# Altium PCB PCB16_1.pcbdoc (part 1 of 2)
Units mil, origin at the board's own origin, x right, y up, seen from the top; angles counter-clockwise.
Board outline 5590 x 7095 mil, 2 copper layers (Top Layer, Bottom Layer); 147 components, 87 nets, 409 pads, 337 vias.
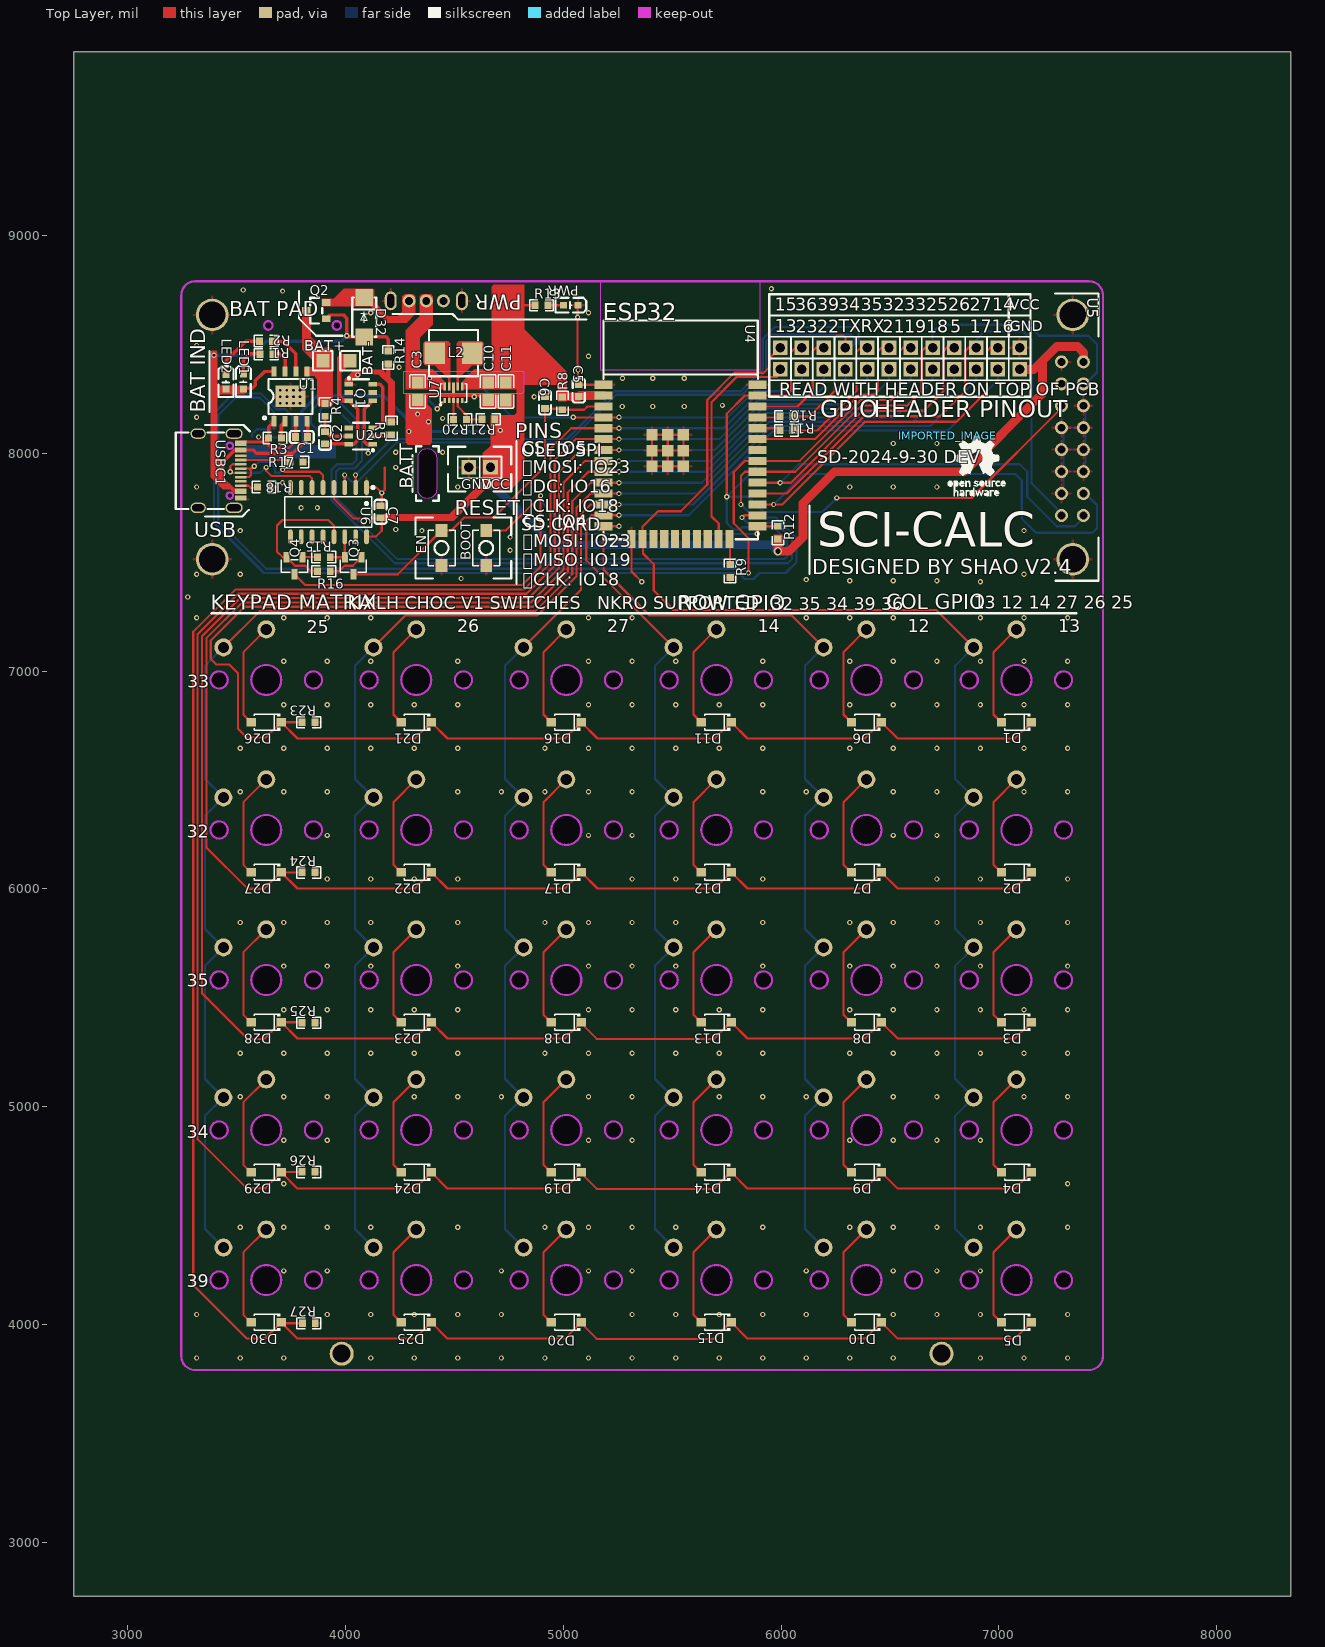
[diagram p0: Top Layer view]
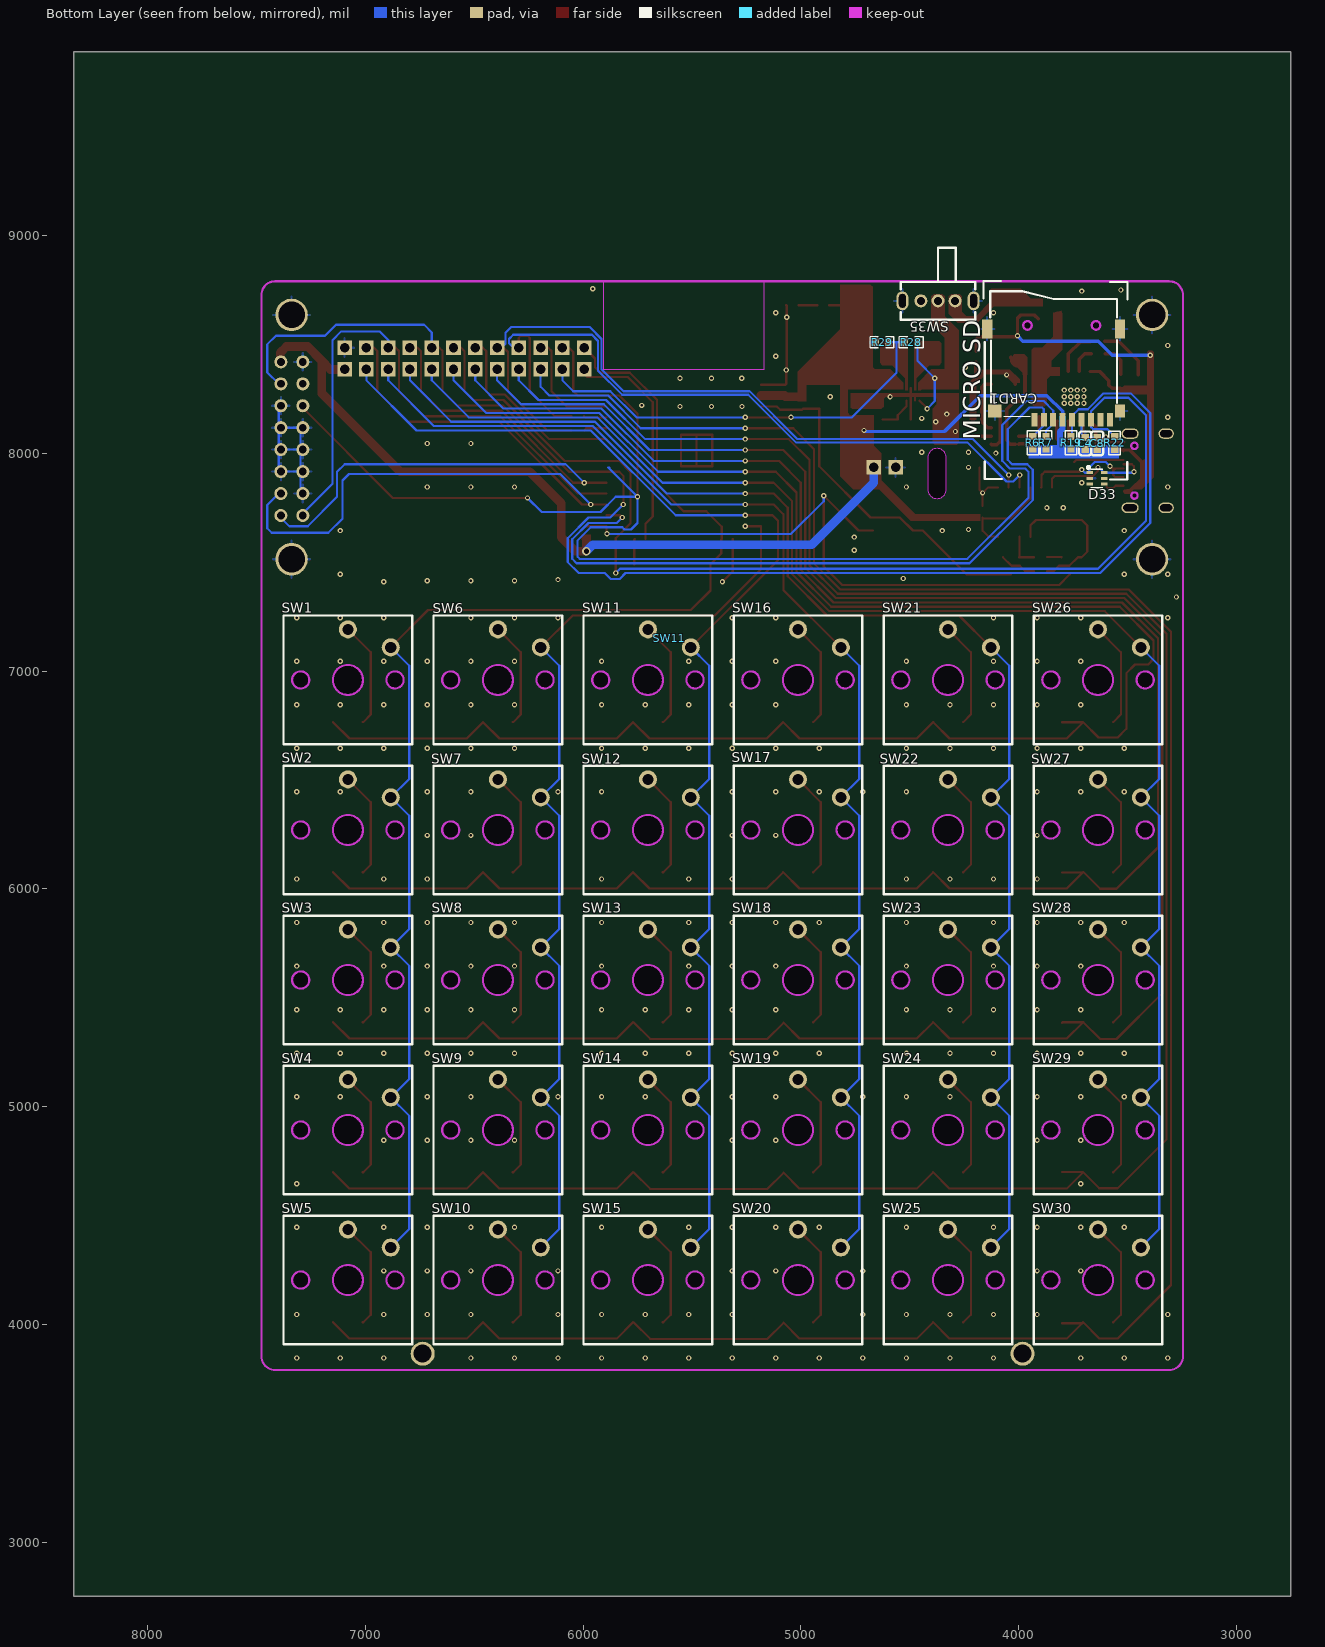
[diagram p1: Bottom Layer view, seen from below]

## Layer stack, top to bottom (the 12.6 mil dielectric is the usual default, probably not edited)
Top Layer: signal copper (thickness not stored)
Dielectric: dielectric 12.6, FR-4, Dk 4.8
Bottom Layer: signal copper (thickness not stored)

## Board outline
8340,2750 2750,2750 2750,9845 8340,9845
cut-out: 4332.03,7834.53 4332.03,7979.53 cw(c4374.53,7979.53) 4374.53,8022.03 cw(c4374.53,7979.53) 4417.03,7979.53 4417.03,7834.53 cw(c4374.53,7834.53) 4374.53,7792.03 cw(c4374.53,7834.53)

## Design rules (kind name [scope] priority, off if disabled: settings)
Clearance safeClearance [All] p1: gap=7 ignorepadtopadclearanceinfootprint=FALSE except(6: Track-Track Track-SMDPad SMDPad-SMDPad Track-THPad SMDPad-THPad THPad-THPad Track-Via SMDPad-Via THPad-Via Via-Via Track-Fill SMDPad-Fill THPad-Fill Via-Fill Fill-Fill Track-Region SMDPad-Region THPad-Region Via-Region Fill-Region Region-Region Track-Poly SMDPad-Poly THPad-Poly Via-Poly Fill-Poly Region-Poly Poly-Poly Track-Text SMDPad-Text THPad-Text Via-Text Fill-Text Region-Text Poly-Text Text-Text Track-Hole SMDPad-Hole THPad-Hole Via-Hole Fill-Hole Region-Hole Poly-Hole Text-Hole; 11.8: Track-Sheet SMDPad-Sheet THPad-Sheet Via-Sheet Fill-Sheet Region-Sheet Poly-Sheet Text-Sheet Sheet-Hole)
DiffPairsRouting differentialPair [All] p1: maxuncoupledlength=10 minlimit=6 maxlimit=50 mostfreqgap=6 toplayer_minwidth=5 toplayer_prefwidth=10 toplayer_maxwidth=100 bottomlayer_minwidth=5 bottomlayer_prefwidth=10 bottomlayer_maxwidth=100
PasteMaskExpansion pasteMaskExpansion [All] p1:
PlaneConnect innerPlane [All] p1: planeconnectstyle=Relief reliefexpansion=20 reliefentries=4 reliefconductorwidth=10 reliefairgap=10
PolygonConnect copperRegion [All] p1: connectstyle=Relief reliefentries=4 reliefconductorwidth=10 polygonreliefangle="90 Angle" airgapwidth=10
RoutingVias viaSize [All] p1: viastyle="Through Hole" holewidth=12.0078 minholewidth=11.811 maxholewidth=236.2204 width=24.0158 minwidth=19.685 maxwidth=393.7008
SolderMaskExpansion solderMaskExpansion [All] p1: useseparateexpansions=TRUE expansion=4 expansionbottom=4
Width trackWidth [All] p1: maxlimit=100 minlimit=5 preferedwidth=10

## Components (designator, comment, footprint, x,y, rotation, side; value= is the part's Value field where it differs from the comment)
5 "2.54-1*1P针" HDR-TH_1P-P2.54-V-M 6795,8485 r0 top
13 "2.54-1*1P针" HDR-TH_1P-P2.54-V-M 5995,8485 r0 top
14 "2.54-1*1P针" HDR-TH_1P-P2.54-V-M 6995,8385 r180 top
15 "2.54-1*1P针" HDR-TH_1P-P2.54-V-M 5995,8385 r0 top
16 "2.54-1*1P针" HDR-TH_1P-P2.54-V-M 6995,8485 r0 top
17 "2.54-1*1P针" HDR-TH_1P-P2.54-V-M 6895,8485 r0 top
18 "2.54-1*1P针" HDR-TH_1P-P2.54-V-M 6695,8485 r0 top
19 "2.54-1*1P针" HDR-TH_1P-P2.54-V-M 6595,8485 r0 top
21 "2.54-1*1P针" HDR-TH_1P-P2.54-V-M 6495,8485 r0 top
22 "2.54-1*1P针" HDR-TH_1P-P2.54-V-M 6195,8485 r0 top
23 "2.54-1*1P针" HDR-TH_1P-P2.54-V-M 6095,8485 r0 top
25 "2.54-1*1P针" HDR-TH_1P-P2.54-V-M 6695,8385 r0 top
26 "2.54-1*1P针" HDR-TH_1P-P2.54-V-M 6795,8385 r0 top
27 "2.54-1*1P针" HDR-TH_1P-P2.54-V-M 6895,8385 r0 top
32 "2.54-1*1P针" HDR-TH_1P-P2.54-V-M 6495,8385 r0 top
33 "2.54-1*1P针" HDR-TH_1P-P2.54-V-M 6595,8385 r0 top
34 "2.54-1*1P针" HDR-TH_1P-P2.54-V-M 6295,8385 r0 top
35 "2.54-1*1P针" HDR-TH_1P-P2.54-V-M 6395,8385 r0 top
36 "2.54-1*1P针" HDR-TH_1P-P2.54-V-M 6095,8385 r180 top
39 "2.54-1*1P针" HDR-TH_1P-P2.54-V-M 6195,8385 r0 top
BOOT "TS-1088-AR02016" SW-SMD_L4.0-W2.9-LS5.0 4645,7565 r90 top
C1 "CL10A106KP8NNNC" C0603 3797.56,8075 r180 top
C2 "CC0603KRX7R9BB104" C0603 3904.99,8071.44 r90 top
C3 "CL21A106KAYNNNE_C15850" C0805 4330,8284.45 r90 top
C4 "CC0603KRX7R9BB104" C0603 3694.07,8045.21 r270 bottom
C5 "CC0603KRX7R9BB104" C0603 5070,8287.56 r270 top
C6 "CL10A106KP8NNNC" C0603 4915,8232.44 r270 top
C7 "CC0603KRX7R9BB104" C0603 4160.16,7731.31 r270 top
C8 "CC0603KRX7R9BB104" C0603 3639.07,8045.33 r270 bottom
C10 "CL21A226MAQNNNE_C45783" C0805 4653.82,8284.45 r90 top
C11 "CL21A226MAQNNNE_C45783" C0805 4735.57,8284.2 r90 top
CARD1 "TF-01A_C2889258" TF-SMD_TF-02 3839.07,8362.77 r0 bottom
D1 "1N4148W_C81598" SOD-123F_L2.7-W1.6-LS3.8-RD 7079.97,6765.24 r180 top
D2 "1N4148W_C81598" SOD-123F_L2.7-W1.6-LS3.8-RD 7079.97,6076.26 r180 top
D3 "1N4148W_C81598" SOD-123F_L2.7-W1.6-LS3.8-RD 7079.97,5387.28 r180 top
D4 "1N4148W_C81598" SOD-123F_L2.7-W1.6-LS3.8-RD 7079.97,4698.31 r180 top
D5 "1N4148W_C81598" SOD-123F_L2.7-W1.6-LS3.8-RD 7079.97,4009.33 r180 top
D6 "1N4148W_C81598" SOD-123F_L2.7-W1.6-LS3.8-RD 6390.99,6765.24 r180 top
D7 "1N4148W_C81598" SOD-123F_L2.7-W1.6-LS3.8-RD 6390.99,6076.26 r180 top
D8 "1N4148W_C81598" SOD-123F_L2.7-W1.6-LS3.8-RD 6390.99,5387.28 r180 top
D9 "1N4148W_C81598" SOD-123F_L2.7-W1.6-LS3.8-RD 6390.99,4698.31 r180 top
D10 "1N4148W_C81598" SOD-123F_L2.7-W1.6-LS3.8-RD 6390.99,4009.33 r180 top
D11 "1N4148W_C81598" SOD-123F_L2.7-W1.6-LS3.8-RD 5702.02,6765.24 r180 top
D12 "1N4148W_C81598" SOD-123F_L2.7-W1.6-LS3.8-RD 5702.02,6076.26 r180 top
D13 "1N4148W_C81598" SOD-123F_L2.7-W1.6-LS3.8-RD 5702.02,5387.28 r180 top
D14 "1N4148W_C81598" SOD-123F_L2.7-W1.6-LS3.8-RD 5702.02,4698.31 r180 top
D15 "1N4148W_C81598" SOD-123F_L2.7-W1.6-LS3.8-RD 5702.02,4009.33 r180 top
D16 "1N4148W_C81598" SOD-123F_L2.7-W1.6-LS3.8-RD 5013.04,6765.24 r180 top
D17 "1N4148W_C81598" SOD-123F_L2.7-W1.6-LS3.8-RD 5013.04,6076.26 r180 top
D18 "1N4148W_C81598" SOD-123F_L2.7-W1.6-LS3.8-RD 5013.04,5387.28 r180 top
D19 "1N4148W_C81598" SOD-123F_L2.7-W1.6-LS3.8-RD 5013.04,4698.31 r180 top
D20 "1N4148W_C81598" SOD-123F_L2.7-W1.6-LS3.8-RD 5013.04,4009.33 r180 top
D21 "1N4148W_C81598" SOD-123F_L2.7-W1.6-LS3.8-RD 4324.06,6765.24 r180 top
D22 "1N4148W_C81598" SOD-123F_L2.7-W1.6-LS3.8-RD 4324.06,6076.26 r180 top
D23 "1N4148W_C81598" SOD-123F_L2.7-W1.6-LS3.8-RD 4324.06,5387.28 r180 top
D24 "1N4148W_C81598" SOD-123F_L2.7-W1.6-LS3.8-RD 4324.06,4698.31 r180 top
D25 "1N4148W_C81598" SOD-123F_L2.7-W1.6-LS3.8-RD 4324.06,4009.33 r180 top
D26 "1N4148W_C81598" SOD-123F_L2.7-W1.6-LS3.8-RD 3635.09,6765.24 r180 top
D27 "1N4148W_C81598" SOD-123F_L2.7-W1.6-LS3.8-RD 3635.09,6076.26 r180 top
D28 "1N4148W_C81598" SOD-123F_L2.7-W1.6-LS3.8-RD 3635.09,5387.28 r180 top
D29 "1N4148W_C81598" SOD-123F_L2.7-W1.6-LS3.8-RD 3635.09,4698.31 r180 top
D30 "1N4148W_C81598" SOD-123F_L2.7-W1.6-LS3.8-RD 3635.09,4009.33 r180 top
D32 "SS34_C8678" DO-214AC_L4.3-W2.7-LS5.3-RD 4085,8625 r270 top
D33 "TPD4E1U06DCKR" SC-70-6_L2.2-W1.3-P0.65-LS2.1-BL 3640,7885 r270 bottom
EN "TS-1088-AR02016" SW-SMD_L4.0-W2.9-LS5.0 4440,7565 r90 top
GND "2.54-1*1P针" HDR-TH_1P-P2.54-V-M 4565,7935 r90 top
GND "2.54-1*1P针" HDR-TH_1P-P2.54-V-M 7095,8485 r0 top
IMPORTED_IMAGE "IMPORTED_IMAGE" IMPORTED_IMAGE 6765,8080 r0 top
L2 "MHCI05030-R47M-R8" IND-SMD_L5.7-W5.4 4495,8460 r0 top
LED1 "19-217/R6C-AL1M2VY/3T" LED0603-R-RD 3530.12,8329.39 r270 top
LED2 "19-217/GHC-YR1S2/3T" LED0603-R-RD 3450.12,8327.89 r270 top
PWR "19-217/R6C-AL1M2VY/3T" LED0603-R-RD 5033.5,8680 r180 top
Q1 "FS8205" SOT-23-6_L2.9-W1.6-P0.95-LS2.8-BR 4069.99,8279 r180 top
Q2 "AO3401A_C15127" SOT-23_L2.9-W1.3-P1.90-LS2.4-BR 3865,8655 r0 top
Q3 "S8050" SOT-23-3_L2.9-W1.3-P1.90-LS2.4-BR 4034.74,7483.33 r90 top
Q4 "S8050" SOT-23-3_L2.9-W1.3-P1.90-LS2.4-BR 3764.74,7483.33 r90 top
R1 "RC0603FR-071KL" R0603 3635.34,8455 r180 top
R2 "RC0603FR-071KL" R0603 3634.66,8515 r0 top
R3 "AR03BTCX5001" R0603 3675,8070 r0 top
R4 "RC0603FR-07100RL" R0603 3905,8199.66 r90 top
R5 "RC0603FR-072KL" R0603 4210,8114.66 r270 top
R6 "RC0603FR-0710KL" R0603 3934.07,8048.11 r270 bottom
R7 "RC0603FR-0710KL" R0603 3874.07,8048.11 r270 bottom
R8 "RC0603FR-0710KL" R0603 4995,8229.66 r90 top
R9 "RC0603FR-0710KL" R0603 5765,7459.66 r90 top
R10 "RC0603FR-07100RL" R0603 6024.66,8170 r180 top
R11 "RC0603FR-07100RL" R0603 6024.66,8105 r180 top
R12 "TR0603B10K0P0525Z" R0603 5985,7635.34 r90 top
R13 "RC0603FR-071KL" R0603 4899.66,8680 r0 top
R14 "RC0603FR-0710KL" R0603 4195,8439.66 r90 top
R15 "TR0603B10K0P0525Z" R0603 3899.4,7458.33 r180 top
R16 "TR0603B10K0P0525Z" R0603 3899.4,7523.33 r0 top
R17 "0603WAF5101T5E" R0603 3774.66,7960 r0 top
R18 "0603WAF5101T5E" R0603 3625,7845 r180 top
R19 "RC0603FR-0710KL" R0603 3759.07,8048.11 r270 bottom
R20 "0603WAF9102T5E" R0603 4524.66,8155 r180 top
R21 "0603WAF5113T5E" R0603 4654.66,8156 r0 top
R22 "RC0603FR-0710KL" R0603 3559.07,8047.43 r270 bottom
R23 "TR0603B10K0P0525Z" R0603 3829.66,6765 r180 top
R24 "TR0603B10K0P0525Z" R0603 3829.66,6075 r180 top
R25 "TR0603B10K0P0525Z" R0603 3829.66,5385 r180 top
R26 "TR0603B10K0P0525Z" R0603 3829.66,4700 r180 top
R27 "TR0603B10K0P0525Z" R0603 3830.34,4005 r180 top
R28 "100k" R0603 4493.24,8509.76 r180 bottom
R29 "100k" R0603 4626.91,8509.76 r180 bottom
RX "2.54-1*1P针" HDR-TH_1P-P2.54-V-M 6395,8485 r180 top
SW1 "CPG135001D01" KEY-TH_CPG135001D0X 6981.58,7150 r180 bottom
SW2 "CPG135001D01" KEY-TH_CPG135001D0X 6981.58,6461.02 r180 bottom
SW3 "CPG135001D01" KEY-TH_CPG135001D0X 6981.58,5772.05 r180 bottom
SW4 "CPG135001D01" KEY-TH_CPG135001D0X 6981.58,5083.07 r180 bottom
SW5 "CPG135001D01" KEY-TH_CPG135001D0X 6981.58,4394.09 r180 bottom
SW6 "CPG135001D01" KEY-TH_CPG135001D0X 6292.61,7150 r180 bottom
SW7 "CPG135001D01" KEY-TH_CPG135001D0X 6292.61,6461.02 r180 bottom
SW8 "CPG135001D01" KEY-TH_CPG135001D0X 6292.61,5772.05 r180 bottom
SW9 "CPG135001D01" KEY-TH_CPG135001D0X 6292.61,5083.07 r180 bottom
SW10 "CPG135001D01" KEY-TH_CPG135001D0X 6292.61,4394.09 r180 bottom
SW11 "CPG135001D01" KEY-TH_CPG135001D0X 5603.63,7150 r180 bottom
SW12 "CPG135001D01" KEY-TH_CPG135001D0X 5603.63,6461.02 r180 bottom
SW13 "CPG135001D01" KEY-TH_CPG135001D0X 5603.63,5772.05 r180 bottom
SW14 "CPG135001D01" KEY-TH_CPG135001D0X 5603.63,5083.07 r180 bottom
SW15 "CPG135001D01" KEY-TH_CPG135001D0X 5603.63,4394.09 r180 bottom
SW16 "CPG135001D01" KEY-TH_CPG135001D0X 4914.65,7150 r180 bottom
SW17 "CPG135001D01" KEY-TH_CPG135001D0X 4914.65,6461.02 r180 bottom
SW18 "CPG135001D01" KEY-TH_CPG135001D0X 4914.65,5772.05 r180 bottom
SW19 "CPG135001D01" KEY-TH_CPG135001D0X 4914.65,5083.07 r180 bottom
SW20 "CPG135001D01" KEY-TH_CPG135001D0X 4914.65,4394.09 r180 bottom
SW21 "CPG135001D01" KEY-TH_CPG135001D0X 4225.68,7150 r180 bottom
SW22 "CPG135001D01" KEY-TH_CPG135001D0X 4225.68,6461.02 r180 bottom
SW23 "CPG135001D01" KEY-TH_CPG135001D0X 4225.68,5772.05 r180 bottom
SW24 "CPG135001D01" KEY-TH_CPG135001D0X 4225.68,5083.07 r180 bottom
SW25 "CPG135001D01" KEY-TH_CPG135001D0X 4225.68,4394.09 r180 bottom
SW26 "CPG135001D01" KEY-TH_CPG135001D0X 3536.7,7150 r180 bottom
SW27 "CPG135001D01" KEY-TH_CPG135001D0X 3536.7,6461.02 r180 bottom
SW28 "CPG135001D01" KEY-TH_CPG135001D0X 3536.7,5772.05 r180 bottom
SW29 "CPG135001D01" KEY-TH_CPG135001D0X 3536.7,5083.07 r180 bottom
SW30 "CPG135001D01" KEY-TH_CPG135001D0X 3536.7,4394.09 r180 bottom
SW35 "SK12D07VG4" SW-TH_SK12D07VG4 4370,8700 r0 bottom
TX "2.54-1*1P针" HDR-TH_1P-P2.54-V-M 6295,8485 r180 top
U1 "4056" ESOP-8_L4.9-W3.9-P1.27-LS6.0-BL-EP 3746.43,8261.1 r0 top
U2 "DW01" SOT-23-6_L2.9-W1.6-P0.95-LS2.8-BR 4069.99,8079 r0 top
U4 "ESP32-WROOM-32E-H4" WIFI-SMD_ESP32-WROOM-32E 5537.78,7960.59 r270 top
U5 "oled" oled3.1 3500,7415 r0 top
U6 "CH340C" SOP-16_L10.0-W3.9-P1.27-LS6.0-BL 3920.76,7729.66 r180 top
U7 "TPS63802DLAR_C2845237" VSON-10_L3.0-W2.0-P0.50-TL 4495,8274.61 r90 top
USBC1 "TYPE-C-31-M-12" USB-C_SMD-TYPE-C-31-M-12 3420,7920 r270 top
VCC "2.54-1*1P针" HDR-TH_1P-P2.54-V-M 4665,7935 r0 top
VCC "2.54-1*1P针" HDR-TH_1P-P2.54-V-M 7095,8385 r0 top

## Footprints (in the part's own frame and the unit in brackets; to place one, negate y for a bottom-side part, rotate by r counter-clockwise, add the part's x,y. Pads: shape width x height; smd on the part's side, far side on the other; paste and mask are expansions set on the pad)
C0603 [mm]
  rect 0.8x0.9 smd: 1(-0.7,0) 2(0.7,0)
  silkscreen extent -1.41,-0.71 1.39,0.72
C0805 [mm]
  rect 1.41x1.35 smd: 1(-1.03,0) 2(1.03,0)
  silkscreen extent -1.96,-0.9 1.96,0.9
DO-214AC_L4.3-W2.7-LS5.3-RD [mil]
  rect 78.7x78.7 smd: 1(-90.5,0) 2(90.6,0)
  silkscreen extent -91,-55 91,55
ESOP-8_L4.9-W3.9-P1.27-LS6.0-BL-EP [mm]
  rect 0.6x1.2 smd: 1(-1.905,-2.908) 2(-0.635,-2.908) 3(0.635,-2.908) 4(1.905,-2.908) 5(1.905,2.908) 6(0.635,2.908) 7(-0.635,2.908) 8(-1.905,2.908)
  rect 3.5x2.5 smd: 9(0,0)
  silkscreen extent -3.2,-2.67 2.55,2.05
HDR-TH_1P-P2.54-V-M [mm]
  rect 1.7x1.7 hole 1.1: 1(0,0)
  silkscreen extent -1.27,-1.27 1.27,1.27
IMPORTED_IMAGE [mil]
  silkscreen extent 0,-277 265,0
IND-SMD_L5.7-W5.4 [mil]
  rect 94.5x98.4 smd: 1(-86.6,0) 2(86.6,0)
  silkscreen extent -112,-106 112,106
KEY-TH_CPG135001D0X [mil]
  round 82.7 hole 51.2: 1(-98.4,41.3) 2(98.4,-41.3)
  Multi-Layer board cut-out: -167.3,-190.9 -160.48,-161.01 -141.36,-137.03 -113.73,-123.73 -83.07,-123.73 -55.44,-137.03 -36.32,-161.01 -29.5,-190.9 -29.5,-190.9 -36.32,-220.79 -55.44,-244.77 -83.07,-258.07 -113.73,-258.07 -141.36,-244.77 -160.48,-220.79 -167.3,-190.9
  Multi-Layer board cut-out: -354.4,-190.9 -350.5,-173.8 -339.57,-160.1 -323.77,-152.49 -306.23,-152.49 -290.43,-160.1 -279.5,-173.8 -275.6,-190.9 -275.6,-190.9 -279.5,-208 -290.43,-221.7 -306.23,-229.31 -323.77,-229.31 -339.57,-221.7 -350.5,-208 -354.4,-190.9
  Multi-Layer board cut-out: 78.7,-190.9 82.6,-173.8 93.53,-160.1 109.33,-152.49 126.87,-152.49 142.67,-160.1 153.6,-173.8 157.5,-190.9 157.5,-190.9 153.6,-208 142.67,-221.7 126.87,-229.31 109.33,-229.31 93.53,-221.7 82.6,-208 78.7,-190.9
  Multi-Layer keep-out circle w10: c-98.4,-190.9 r68.9
  Multi-Layer keep-out circle w10: c-315,-190.9 r39.4
  Multi-Layer keep-out circle w10: c118.1,-190.9 r39.4
  silkscreen extent -394,-486 197,104
LED0603-R-RD [mm]
  rect 0.8x0.8 smd: 1(0.851,0) 2(-0.851,0)
  silkscreen extent -1.82,-0.86 1.77,0.86
oled3.1 [mil]
  round 60 hole 35.98: 1(3787.01,1004.8) 2(3887.8,1004.8) 3(3787.01,904.02) 4(3887.8,904.02) 5(3787.01,803.23) 6(3887.8,803.23) 7(3787.01,702.44) 8(3887.8,702.44) 9(3787.01,601.65) 10(3887.8,601.65) 11(3787.01,500.87) 12(3887.8,500.87) 13(3787.01,400.08) 14(3887.8,400.08) 15(3787.01,299.29) 16(3887.8,299.29)
  silkscreen extent 3758,0 3957,1319
R0603 [mil]
  rect 31.75x34.02 smd: 1(-29.66,0) 2(29.66,0)
  silkscreen extent -55,-26 55,26
SC-70-6_L2.2-W1.3-P0.65-LS2.1-BL [mm]
  rect 0.35x0.78 smd: 1(-0.65,-0.84) 2(0,-0.84) 3(0.65,-0.84) 4(0.65,0.84) 5(0,0.84) 6(-0.65,0.84)
  silkscreen extent -1.43,-1.14 1.08,0.7
SOD-123F_L2.7-W1.6-LS3.8-RD [mm]
  rect 1.1x1 smd: 1(-1.735,0) 2(1.735,0)
  silkscreen extent -1.6,-1 1.38,1
SOP-16_L10.0-W3.9-P1.27-LS6.0-BL [mm]
  oval 0.56x1.745 smd: 1(-4.445,-2.872) 2(-3.175,-2.872) 3(-1.905,-2.872) 4(-0.635,-2.872) 5(0.635,-2.872) 6(1.905,-2.872) 7(3.175,-2.872) 8(4.445,-2.872) 9(4.445,2.872) 10(3.175,2.872) 11(1.905,2.872) 12(0.635,2.872) 13(-0.635,2.872) 14(-1.905,2.872) 15(-3.175,2.872) 16(-4.445,2.872)
  silkscreen extent -5.33,-3.02 5.08,1.77
SOT-23-3_L2.9-W1.3-P1.90-LS2.4-BR [mm]
  rect 1.25x0.7 smd: 1(1,-0.95) 2(1,0.95) 3(-1,0)
  silkscreen extent -0.73,-1.53 0.73,1.53
SOT-23-6_L2.9-W1.6-P0.95-LS2.8-BR [mm]
  rect 1x0.55 smd: 1(1.4,-0.95) 2(1.4,0) 3(1.4,0.95) 4(-1.4,0.95) 5(-1.4,0) 6(-1.4,-0.95)
  silkscreen extent -0.9,-1.78 1.52,1.55
SOT-23_L2.9-W1.3-P1.90-LS2.4-BR [mm]
  rect 1x0.8 smd: 1(1.15,-0.95) 2(1.15,0.95) 3(-1.15,0)
  silkscreen extent -0.7,-1.5 0.7,1.5
SW-SMD_L4.0-W2.9-LS5.0 [mm]
  rect 1.53x1.36 smd: 1(-2.035,0) 2(2.035,0)
  silkscreen extent -2.08,-1.58 2.08,1.58
SW-TH_SK12D07VG4 [mil]
  round 60 hole 36: 1(-78.7,0) 2(0,0) 3(78.7,0)
  oval 55.1x86.6 hole 31.5 slot 63 at 90 deg: 4(163.4,0) 5(-163.4,0)
  silkscreen extent -171,-244 171,87
TF-SMD_TF-02 [mm]
  rect 0.7x1.6 smd: 1(2.245,5.3) 2(1.145,5.3) 3(0.046,5.3) 4(-1.054,5.3) 5(-2.154,5.3) 6(-3.255,5.3) 7(-4.354,5.3) 8(-5.454,5.3) 9(-6.554,5.3)
  rect 1.2x1.5 smd: 10(-7.754,4.3)
  rect 1.2x2.2 smd: 11(-7.746,-5.3) 12(7.754,-5.3)
  rect 1.6x1.5 smd: 13(6.854,4.3)
  Multi-Layer board cut-out: 3.554,-5.7 3.504,-5.917 3.366,-6.091 3.165,-6.187 2.943,-6.188 2.742,-6.091 2.603,-5.917 2.554,-5.7 2.554,-5.7 2.621,-5.45 2.804,-5.267 3.054,-5.2 3.304,-5.267 3.487,-5.45 3.554,-5.7
  Multi-Layer board cut-out: -4.446,-5.7 -4.496,-5.917 -4.634,-6.091 -4.835,-6.187 -5.057,-6.188 -5.258,-6.091 -5.397,-5.917 -5.446,-5.7 -5.446,-5.7 -5.379,-5.45 -5.196,-5.267 -4.946,-5.2 -4.696,-5.267 -4.513,-5.45 -4.446,-5.7
  Multi-Layer keep-out circle w0.254: c3.054,-5.7 r0.5
  Multi-Layer keep-out circle w0.254: c-4.946,-5.7 r0.5
  silkscreen extent -7.41,-9.68 7.39,4.93
USB-C_SMD-TYPE-C-31-M-12 [mm]
  oval 1.2x2 hole 0.8 slot 1.6 at 90 deg: 0(-4.325,1.716) 0(4.325,1.716)
  oval 1.2x1.8 hole 0.8 slot 1.4 at 90 deg: 0(-4.325,-2.484) 0(4.325,-2.484)
  rect 0.3x1.3 smd: A1(-3.35,2.484) A4(-2.55,2.484) A5(-1.25,2.484) A6(-0.25,2.484) A7(0.25,2.484) A8(1.25,2.484) A9(2.55,2.484) A12(3.35,2.484) B1(3.05,2.484) B4(2.25,2.484) B5(1.75,2.484) B6(0.75,2.484) B7(-0.75,2.484) B8(-1.75,2.484) B9(-2.25,2.484) B12(-3.05,2.484)
  Multi-Layer board cut-out: -2.9,1.591 -3.085,1.539 -3.22,1.402 -3.27,1.216 -3.22,1.03 -3.085,0.893 -2.9,0.841 -2.9,0.841 -2.715,0.893 -2.58,1.03 -2.53,1.216 -2.58,1.402 -2.715,1.539 -2.9,1.591
  Multi-Layer board cut-out: 2.9,1.591 2.715,1.539 2.58,1.402 2.53,1.216 2.58,1.03 2.715,0.893 2.9,0.841 2.9,0.841 3.085,0.893 3.22,1.03 3.27,1.216 3.22,1.402 3.085,1.539 2.9,1.591
  Multi-Layer keep-out circle w0.254: c-2.9,1.216 r0.375
  Multi-Layer keep-out circle w0.254: c2.9,1.216 r0.375
  silkscreen extent -4.47,-5.08 4.47,0.5
VSON-10_L3.0-W2.0-P0.50-TL [mm]
  rect 0.6x0.3 smd: 1(-0.825,1) 2(-0.825,0.5) 3(-0.825,0) 4(-0.825,-0.5) 5(-0.825,-1)
  rect 0.9x0.3 smd: 6(0.825,-1) 7(0.825,-0.5) 9(0.825,0.5) 10(0.825,1)
  rect 1.3x0.3 smd: 8(0.625,0)
  silkscreen extent -1.42,-1.52 1.14,1.62
WIFI-SMD_ESP32-WROOM-32E [mm]
  rect 0.95x2.1 smd: 1(-9.003,-9) 2(-7.733,-9) 3(-6.463,-9) 4(-5.193,-9) 5(-3.923,-9) 6(-2.653,-9) 7(-1.383,-9) 8(-0.113,-9) 9(1.157,-9) 10(2.427,-9) 11(3.697,-9) 12(4.967,-9) 13(6.237,-9) 14(7.507,-9) 25(7.507,9) 26(6.237,9) 27(4.967,9) 28(3.697,9) 29(2.427,9) 30(1.157,9) 31(-0.113,9) 32(-1.383,9) 33(-2.653,9) 34(-3.923,9) 35(-5.193,9) 36(-6.463,9) 37(-7.733,9) 38(-9.003,9)
  rect 2.1x0.95 smd: 15(9.003,-5.715) 16(9.003,-4.445) 17(9.003,-3.175) 18(9.003,-1.905) 19(9.003,-0.635) 20(9.003,0.635) 21(9.003,1.905) 22(9.003,3.175) 23(9.003,4.445) 24(9.003,5.715)
  rect 1.33x1.33 smd: 39(-3.153,0.335) 39(-3.153,-1.5) 39(-3.153,-3.335) 39(-1.318,0.335) 39(-1.318,-1.5) 39(-1.318,-3.335) 39(0.517,0.335) 39(0.517,-1.5) 39(0.517,-3.335)
  silkscreen extent -16.48,-9 9.02,9.02

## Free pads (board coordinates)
  round 149.61 hole 122.05: 1(3386.77,7513.43) 1(3386.77,8635.47) 1(7338.74,7513.43) 1(7338.74,8635.47)
  round 110.24 hole 82.68: 4(3981.58,3865) 4(6736.58,3865)
  rect 60x60 smd: 40(3895,8425) 40(4020,8425)

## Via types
v1: diameter 24.41, hole 11.81, Top Layer to Bottom Layer, 261 vias
v2: diameter 24.02, hole 12.01, Top Layer to Bottom Layer, 75 vias
v3: diameter 39.37, hole 23.62, Top Layer to Bottom Layer, 1 vias

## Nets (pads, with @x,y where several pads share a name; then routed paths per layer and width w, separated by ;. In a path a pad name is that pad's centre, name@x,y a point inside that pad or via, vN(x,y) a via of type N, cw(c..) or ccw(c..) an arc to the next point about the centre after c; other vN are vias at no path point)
$1N6151: R1.1 U1.7 | length 121.2
  Top Layer w15.75: R1.1@3667.11,8457.89 3695.12,8457.89 3721.43,8431.57 U1.7@3721.43,8375.6
$1N9442: R2.2 U1.6 | length 205.6
  Top Layer w15.75: R2.2@3670.12,8512.89 3715.12,8512.89 3771.43,8456.57 U1.6@3771.43,8375.6
$1N11042: pad.40@3895,8425 Q2.3 R4.2 U1.5 | length 190.7
  Top Layer w15.75: 3924.99,8228.32 pad.40@3924.99,8419
$1N12169: C2.1 pad.40@4020,8425 Q1.3 U2.6 | length 596.8
  Top Layer w15.75: C2.1@3909.99,8043.88 3997.59,8043.88 U2.6@3999.87,8041.6 ; U2.6@4014.87,8041.6 4037.59,8041.6 4055,8059.01 4055,8201.48 Q1.3@4014.87,8241.6
  Top Layer w19.68: pad.40@4008.79,8413.79 3970,8375 3970,8260 3988.4,8241.6 Q1.3@4014.87,8241.6 ; pad.40@4020,8425 pad.40@4035,8440
  Top Layer w40: pad.40@4008.79,8413.79 pad.40@4020,8425
$1N13027: R5.2 U2.2 | length 85.2
  Top Layer w15.75: U2.2@4125.11,8079 4209.31,8079 R5.2@4209.99,8079.68
$1N35276: R10.2 U4.35 | length 104.9
  Top Layer w10: U4.35@5892.11,8165.02 5990.02,8165.02 R10.2@5995,8170
$1N35352: R11.2 U4.34 | length 107
  Top Layer w10: U4.34@5892.11,8115.02 5984.98,8115.02 R11.2@5995,8105
$1N60278: PWR.1 R13.2 | length 85.7
  Top Layer w10: R13.2@4924.32,8680 PWR.1@5010,8680
$1N61238: C2.2 R4.1 U2.5 | length 168.2
  Top Layer w15.75: C2.2@3904.99,8099 R4.1@3904.99,8169 ; C2.2@3909.99,8099 3929.99,8079 U2.5@3999.87,8079
$1N94408: D32.1 Q2.2 SW35.1 | length 429.4
  Top Layer w10: 3961,8692.4 3975.28,8692.4 3998.37,8715.5 D32.1@4085,8715.5 4180.5,8620 4240,8620 4291.3,8671.3 SW35.1@4291.3,8700
$1N98965: Q3.1 R15.1 | length 169.7
  Top Layer w10: R15.1@3929.06,7458.33 3969.74,7458.33 3994.74,7483.33 4032.77,7483.33 Q3.1@4072.14,7522.7
$1N99052: Q4.1 R16.1 | length 67.9
  Top Layer w10: Q4.1@3802.14,7522.7 3802.77,7523.33 R16.1@3869.74,7523.33
$1N107038: R17.1 USBC1.A5 | length 231
  Top Layer w10: USBC1.A5@3517.8,7969.21 3735.79,7969.21 R17.1@3745,7960
$1N107257: R18.2 USBC1.B5 | length 83.3
  Top Layer w10: USBC1.B5@3517.8,7851.1 3553.9,7851.1 3563.9,7841.1 3591.44,7841.1 R18.2@3595.34,7845
$1N116897: L2.1 U7.9
$1N116990: L2.2 U7.7
$1N121375: R20.1 R21.1 U7.4 | length 174.8
  Top Layer w10: U7.4@4514.69,8242.12 4514.69,8215.31 4555,8175 4555,8155.68 R20.1@4554.32,8155 R21.1@4625,8155
$1N140289: LED1.2 R1.2 | length 149.4
  Top Layer w15.75: LED1.2@3530.12,8362.89 3530.12,8427.89 3560.12,8457.89 R1.2@3602.11,8457.89
$1N141203: LED2.2 R2.1 | length 255.8
  Top Layer w15.75: LED2.2@3450.12,8361.39 3450.12,8425.12 3540,8515 R2.1@3605,8515
$1N141745: R3.2 U1.2 | length 83.7
  Top Layer w15.75: R3.2@3704.32,8070 3704.32,8129.49 U1.2@3721.43,8146.6
$1N191709: D1.2 SW1.1 | length 485.8
  Top Layer w10: D1.2@7011.66,6765.24 7009.76,6765.24 6975,6800 6975,7086.32 SW1.1@7079.98,7191.3
$1N192023: D2.2 SW2.1 | length 485.8
  Top Layer w10: D2.2@7011.66,6076.26 7009.76,6076.26 6975,6111.02 6975,6397.34 SW2.1@7079.98,6502.32
$1N192337: D3.2 SW3.1 | length 485.8
  Top Layer w10: D3.2@7011.66,5387.28 7009.76,5387.28 6975,5422.05 6975,5708.37 SW3.1@7079.98,5813.35
$1N192651: D4.2 SW4.1 | length 485.8
  Top Layer w10: D4.2@7011.66,4698.31 7009.76,4698.31 6975,4733.07 6975,5019.39 SW4.1@7079.98,5124.37
$1N192965: D5.2 SW5.1 | length 485.8
  Top Layer w10: D5.2@7011.66,4009.33 7009.76,4009.33 6975,4044.09 6975,4330.41 SW5.1@7079.98,4435.39
$1N193735: D6.2 SW6.1 | length 485.8
  Top Layer w10: D6.2@6322.69,6765.24 6320.79,6765.24 6286.02,6800 6286.02,7086.32 SW6.1@6391.01,7191.3
$1N193736: D7.2 SW7.1 | length 485.8
  Top Layer w10: D7.2@6322.69,6076.26 6320.79,6076.26 6286.02,6111.02 6286.02,6397.34 SW7.1@6391.01,6502.32
$1N193737: D8.2 SW8.1 | length 485.8
  Top Layer w10: D8.2@6322.69,5387.28 6320.79,5387.28 6286.02,5422.05 6286.02,5708.37 SW8.1@6391.01,5813.35
$1N193738: D9.2 SW9.1 | length 485.8
  Top Layer w10: D9.2@6322.69,4698.31 6320.79,4698.31 6286.02,4733.07 6286.02,5019.39 SW9.1@6391.01,5124.37
$1N193739: D10.2 SW10.1 | length 485.8
  Top Layer w10: D10.2@6322.69,4009.33 6320.79,4009.33 6286.02,4044.09 6286.02,4330.41 SW10.1@6391.01,4435.39
$1N194509: D11.2 SW11.1 | length 485.8
  Top Layer w10: D11.2@5633.71,6765.24 5631.81,6765.24 5597.05,6800 5597.05,7086.32 SW11.1@5702.03,7191.3
$1N194510: D12.2 SW12.1 | length 485.8
  Top Layer w10: D12.2@5633.71,6076.26 5631.81,6076.26 5597.05,6111.02 5597.05,6397.34 SW12.1@5702.03,6502.32
$1N194511: D13.2 SW13.1 | length 485.8
  Top Layer w10: D13.2@5633.71,5387.28 5631.81,5387.28 5597.05,5422.05 5597.05,5708.37 SW13.1@5702.03,5813.35
$1N194512: D14.2 SW14.1 | length 485.8
  Top Layer w10: D14.2@5633.71,4698.31 5631.81,4698.31 5597.05,4733.07 5597.05,5019.39 SW14.1@5702.03,5124.37
$1N194513: D15.2 SW15.1 | length 485.8
  Top Layer w10: D15.2@5633.71,4009.33 5631.81,4009.33 5597.05,4044.09 5597.05,4330.41 SW15.1@5702.03,4435.39
$1N195283: D16.2 SW16.1 | length 485.8
  Top Layer w10: D16.2@4944.73,6765.24 4942.83,6765.24 4908.07,6800 4908.07,7086.32 SW16.1@5013.05,7191.3
$1N195284: D17.2 SW17.1 | length 485.8
  Top Layer w10: D17.2@4944.73,6076.26 4942.83,6076.26 4908.07,6111.02 4908.07,6397.34 SW17.1@5013.05,6502.32
$1N195285: D18.2 SW18.1 | length 485.8
  Top Layer w10: D18.2@4944.73,5387.28 4942.83,5387.28 4908.07,5422.05 4908.07,5708.37 SW18.1@5013.05,5813.35
$1N195286: D19.2 SW19.1 | length 485.8
  Top Layer w10: D19.2@4944.73,4698.31 4942.83,4698.31 4908.07,4733.07 4908.07,5019.39 SW19.1@5013.05,5124.37
$1N195287: D20.2 SW20.1 | length 485.8
  Top Layer w10: D20.2@4944.73,4009.33 4942.83,4009.33 4908.07,4044.09 4908.07,4330.41 SW20.1@5013.05,4435.39
$1N196057: D21.2 SW21.1 | length 485.8
  Top Layer w10: D21.2@4255.76,6765.24 4253.86,6765.24 4219.09,6800 4219.09,7086.32 SW21.1@4324.08,7191.3
$1N196058: D22.2 SW22.1 | length 485.8
  Top Layer w10: D22.2@4255.76,6076.26 4253.86,6076.26 4219.09,6111.02 4219.09,6397.34 SW22.1@4324.08,6502.32
$1N196059: D23.2 SW23.1 | length 485.8
  Top Layer w10: D23.2@4255.76,5387.28 4253.86,5387.28 4219.09,5422.05 4219.09,5708.37 SW23.1@4324.08,5813.35
$1N196060: D24.2 SW24.1 | length 485.8
  Top Layer w10: D24.2@4255.76,4698.31 4253.86,4698.31 4219.09,4733.07 4219.09,5019.39 SW24.1@4324.08,5124.37
$1N196061: D25.2 SW25.1 | length 485.8
  Top Layer w10: D25.2@4255.76,4009.33 4253.86,4009.33 4219.09,4044.09 4219.09,4330.41 SW25.1@4324.08,4435.39
$1N196831: D26.2 SW26.1 | length 485.8
  Top Layer w10: D26.2@3566.78,6765.24 3564.88,6765.24 3530.12,6800 3530.12,7086.32 SW26.1@3635.1,7191.3
$1N196832: D27.2 SW27.1 | length 485.8
  Top Layer w10: D27.2@3566.78,6076.26 3564.88,6076.26 3530.12,6111.02 3530.12,6397.34 SW27.1@3635.1,6502.32
$1N196833: D28.2 SW28.1 | length 485.8
  Top Layer w10: D28.2@3566.78,5387.28 3564.88,5387.28 3530.12,5422.05 3530.12,5708.37 SW28.1@3635.1,5813.35
$1N196834: D29.2 SW29.1 | length 485.8
  Top Layer w10: D29.2@3566.78,4698.31 3564.88,4698.31 3530.12,4733.07 3530.12,5019.39 SW29.1@3635.1,5124.37
$1N196835: D30.2 SW30.1 | length 485.8
  Top Layer w10: D30.2@3566.78,4009.33 3564.88,4009.33 3530.12,4044.09 3530.12,4330.41 SW30.1@3635.1,4435.39
+3.3V: C4.2 C5.2 C7.2 C8.2 C10.2 C11.2 CARD1.4 R6.2 R7.2 R8.2 R12.1 R13.1 R19.2 R21.2 R22.2 U4.2 U5.2 U6.4 U6.16 U7.6 VCC.1 | length 5667.8
  Top Layer w10: U6.4@3945.76,7842.75 3945.76,7791.4 4037.16,7700 4161.41,7700 4165.16,7703.75 4165.16,7643.75 4139.74,7618.33 4097.51,7618.33 U6.16@4095.76,7616.57 ; 4795,8685 4800,8680 R13.1@4870,8680
  Top Layer w40: R8.2@4995,8259.32 4995.68,8260 C5.2@5070,8260 5075,8265 U4.2@5183.44,8265.02 ; R12.1@5985,7605.68 v3(5985,7550) 6036.16,7550 6100,7613.84 6100,7770 6245,7915 6840,7915 7200,8275 7200,8425 ; VCC.1@7095,8385 7160,8385 7200,8425 ; U5.2@7397.8,8419.8 7390,8427.6 7390,8462.2 7362.2,8490 7265,8490 7200,8425
  Bottom Layer w10: v2@4705,8100 v2(4710,8105)
  Bottom Layer w15.75: CARD1.4@3797.56,8169.11 3797.56,8192.56 3870,8265 4175,8265 4340,8100 v2@4705,8100
  Bottom Layer w27.56: CARD1.4@3797.56,8169.11 3797.56,8112.44 3810,8100 3810,7990
  Bottom Layer w40: VCC.1@4665,7935 4665,7865 4950,7580 5955,7580 v3(5985,7550)
DN: D33.6 U6.6 USBC1.A7 USBC1.B7 | length 585.5
  Top Layer w10: USBC1.A7@3517.8,7910.16 3475.21,7910.16 v2(3470,7915.37) 3470,7940 3479.53,7949.53 USBC1.B7@3517.8,7949.53 ; v2(3635,7935) 3635,7920 3660,7895 3835,7895 3845.76,7884.24 U6.6@3845.76,7842.75
  Bottom Layer w10: v2(3470,7915.37) 3474.78,7910.59 D33.6@3606.93,7910.59 3631.34,7935 v2(3635,7935)
DP: D33.1 U6.5 USBC1.A6 USBC1.B6 | length 586.1
  Top Layer w10: USBC1.B6@3517.8,7890.47 3555.47,7890.47 3565,7900 3565,7920 3555.16,7929.84 ; USBC1.A6@3517.8,7929.84 3555.16,7929.84 ; v2(3580,7940) 3570,7930 3555.32,7930 3555.16,7929.84 ; v2(3710,7925) 3720,7915 3880,7915 3895,7900 3895,7843.51 U6.5@3895.76,7842.75
  Bottom Layer w10: v2(3580,7940) 3600,7960 3650,7960 3675,7935 3675,7912.52 D33.1@3673.07,7910.59 3695.59,7910.59 v2(3710,7925)
DTR: Q4.2 R15.2 U6.13 | length 675.5
  Top Layer w10: R15.2@3869.74,7458.33 3839.74,7458.33 3814.74,7483.33 3766.71,7483.33 Q4.2@3727.34,7522.7 3710.37,7522.7 3684.74,7548.33 3684.74,7668.33 3709.74,7693.33 3920.35,7693.33 3945.76,7667.92 U6.13@3945.76,7616.57
EN: C6.2 EN.2 Q3.3 R8.1 U4.3 | length 1632.3
  Top Layer w10: Q3.3@4034.74,7443.96 4238.84,7443.96 EN.2@4440,7645.12 4485.12,7645.12 4545,7705 4680,7705 4915,7940 C6.2@4915,8204.88 4990.08,8204.88 R8.1@4995,8200 5014.99,8199.99 ; 5014.88,8199.88 5014.99,8199.99 ; U4.3@5183.44,8215.02 5110,8215 5095,8200 5019.88,8200 ; 5015,8200 5019.88,8200 ; 5014.99,8199.99 5019.88,8200
GND: 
